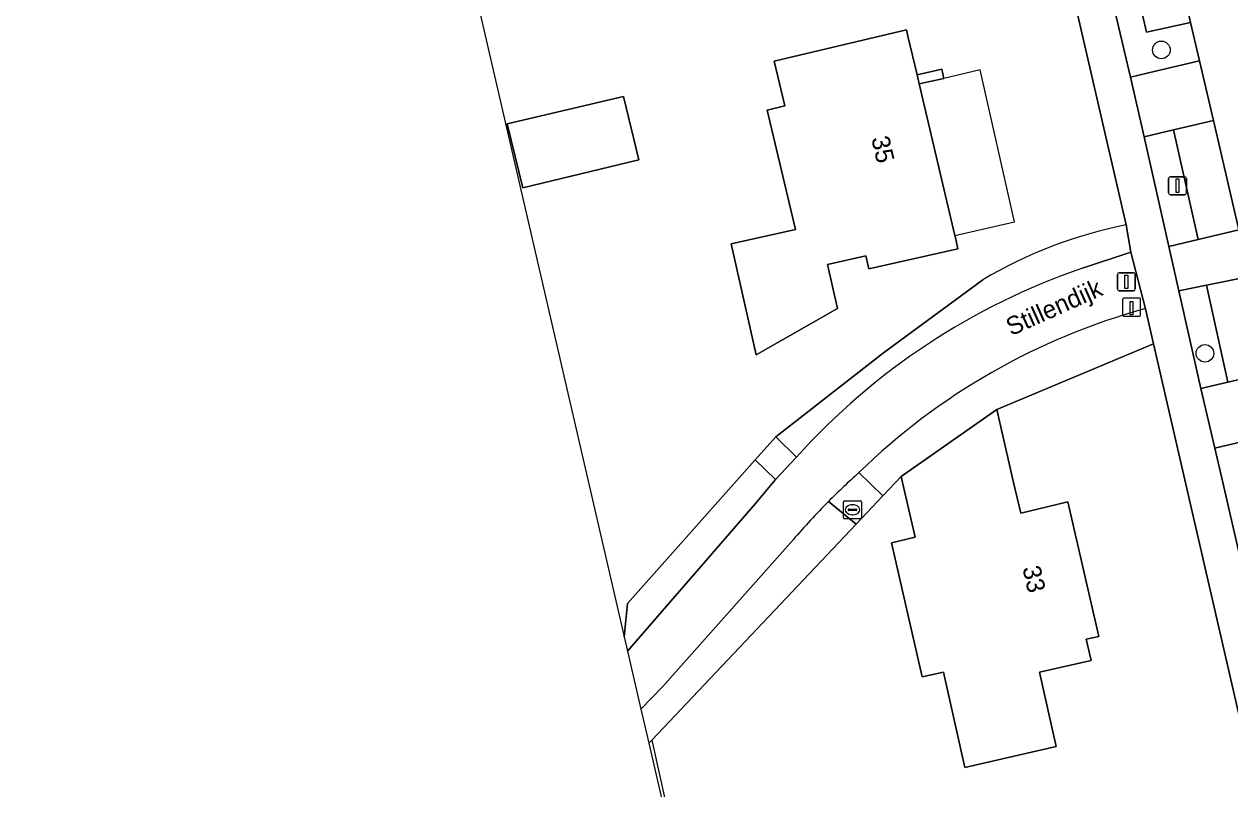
# Model space of a CAD drawing. Extents: x 156412 to 157779, y 382335 to 383768.
# Drawn here: x 156633.8 to 156700.6, y 382733 to 382775.4 of the extents above; entities that cross this region are included whole.
import ezdxf

# ---------------------------------------------------------------- set-up
doc = ezdxf.new("R2010")
doc.units = 0
for name, color, linetype in [('IMGEO_Afsluitpaal', 7, 'Continuous'), ('IMGEO_Berm_groen', 7, 'Continuous'), ('IMGEO_Boom', 7, 'Continuous'), ('IMGEO_Erf', 7, 'Continuous'), ('IMGEO_Fietspad_gesloten', 7, 'Continuous'), ('IMGEO_Fietspad_open', 7, 'Continuous'), ('IMGEO_Hek', 7, 'Continuous'), ('IMGEO_Kolk', 7, 'Continuous'), ('IMGEO_Lichtmast', 7, 'Continuous'), ('IMGEO_Muur', 7, 'Continuous'), ('IMGEO_Openbare_ruimte_label', 7, 'Continuous'), ('IMGEO_Paal', 7, 'Continuous'), ('IMGEO_Pand', 7, 'Continuous'), ('IMGEO_Pand_nummerreeks', 7, 'Continuous'), ('IMGEO_Pand_overbouw', 7, 'Continuous'), ('IMGEO_Parkeervlak_halfverhard', 7, 'Continuous'), ('IMGEO_Rijbaan_lokaal_gesloten', 7, 'Continuous'), ('IMGEO_Rijbaan_lokaal_open', 7, 'Continuous'), ('IMGEO_Voetpad_open', 7, 'Continuous')]:
    doc.layers.add(name, color=color, linetype=linetype)

msp = doc.modelspace()

# ---------------------------------------------------------------- linework, layer by layer
at = {"layer": 'IMGEO_Afsluitpaal'}
for p, q in [((156694.397, 382760.72), (156694.397, 382761.52)), ((156694.397, 382761.52), (156694.397, 382760.72)), ((156694.497, 382761.62), (156695.287, 382761.62)), ((156695.287, 382761.62), (156694.497, 382761.62)), ((156695.387, 382761.52), (156695.387, 382760.72)), ((156695.387, 382760.72), (156695.387, 382761.52)), ((156695.287, 382760.62), (156694.497, 382760.62)), ((156694.497, 382760.62), (156695.287, 382760.62))]:
    msp.add_line(p, q, dxfattribs=at)
msp.add_lwpolyline([(156694.817, 382761.495), (156694.967, 382761.495), (156694.967, 382760.745), (156694.817, 382760.745), (156694.817, 382761.495)], dxfattribs=at)
for centre, start, end in [((156694.497, 382761.52), 90, 180), ((156694.497, 382761.52), 90, 180), ((156695.287, 382761.52), 0, 90), ((156695.287, 382761.52), 360, 90), ((156694.497, 382760.72), 180, 270), ((156694.497, 382760.72), 180, 270), ((156695.287, 382760.72), 270, 0), ((156695.287, 382760.72), 270, 0)]:
    msp.add_arc(centre, 0.1, start, end, dxfattribs=at)
at = {"layer": 'IMGEO_Berm_groen'}
for points in [[(156695.215, 382789.506), (156692.782, 382788.931), (156691.321, 382788.585), (156695.122, 382772.473), (156696.517, 382772.802), (156698.95, 382773.376), (156698.458, 382775.501), (156696.018, 382774.957), (156693.309, 382786.654), (156695.744, 382787.222)], [(156697.512, 382769.539), (156695.881, 382769.156), (156697.255, 382763.084), (156698.872, 382763.466)], [(156699.337, 382760.93), (156697.809, 382760.618), (156699.031, 382755.211), (156700.512, 382755.552)], [(156701.278, 382752.242), (156699.805, 382751.887), (156700.241, 382750), (156701.911, 382742.773), (156703.385, 382743.12)], [(156667.231, 382740.642), (156674.321, 382748.836), (156675.444, 382750.152), (156674.316, 382751.245), (156667.239, 382743.282), (156667.046, 382741.442)]]:
    msp.add_lwpolyline(points, close=True, dxfattribs=at)
for points in [[(156692.46, 382761.877), (156695.147, 382762.767), (156694.882, 382764.275)], [(156686.93, 382761.227), (156681.422, 382757.184), (156675.463, 382752.525), (156676.602, 382751.4)], [(156696.399, 382757.676), (156695.949, 382759.629)], [(156680.063, 382750.539), (156681.391, 382749.254), (156682.407, 382750.328), (156687.706, 382754.041), (156696.399, 382757.676)], [(156668.411, 382735.538), (156668.582, 382735.705), (156679.903, 382747.679), (156678.372, 382748.938)], [(156676.416, 382746.819), (156669.164, 382738.669), (156667.976, 382737.419), (156668.411, 382735.538)]]:
    msp.add_lwpolyline(points, dxfattribs=at)
for centre, radius, start, end in [((156699.833, 382739.461), 25.304, 101.28401, 120.65963), ((156704.737, 382726.055), 37.868, 108.91757, 137.986), ((156705.623, 382724.296), 36.634, 105.31209, 134.24445), ((156710.589, 382717.237), 45.198, 135.46248, 139.11874)]:
    msp.add_arc(centre, radius, start, end, dxfattribs=at)
at = {"layer": 'IMGEO_Boom'}
for centre in [(156696.837, 382773.973), (156699.253, 382757.152)]:
    msp.add_circle(centre, 0.489, dxfattribs=at)
at = {"layer": 'IMGEO_Erf'}
for points in [[(156662.663, 382894.621), (156655.658, 382892.624), (156652.152, 382891.665), (156646.148, 382889.742), (156640.021, 382887.678), (156636.864, 382886.529), (156633.896, 382885.409), (156633.769, 382885.37), (156667.046, 382741.442)], [(156694.882, 382764.275), (156665.21, 382892.732)], [(156667.046, 382741.442), (156667.239, 382743.282), (156674.316, 382751.245), (156675.463, 382752.525), (156681.422, 382757.184), (156686.93, 382761.227)], [(156708.634, 382704.563), (156696.399, 382757.676), (156687.706, 382754.041), (156688.641, 382750), (156689.036, 382748.295), (156691.645, 382748.927), (156693.368, 382741.448), (156692.667, 382741.304), (156692.938, 382740.131), (156690.082, 382739.476), (156690.997, 382735.351), (156685.938, 382734.188), (156684.748, 382739.475), (156683.577, 382739.212), (156681.866, 382746.654), (156683.182, 382746.956), (156682.482, 382750), (156682.407, 382750.328), (156681.391, 382749.254), (156679.903, 382747.679), (156668.582, 382735.705), (156668.411, 382735.538), (156678.18, 382693.285), (156690.465, 382640.147)]]:
    msp.add_lwpolyline(points, dxfattribs=at)
for points in [[(156682.696, 382775.089), (156682.778, 382774.743), (156683.29, 382772.589), (156684.664, 382772.906), (156684.778, 382772.397), (156683.405, 382772.098), (156685.382, 382763.692), (156685.394, 382763.64), (156685.55, 382762.951), (156680.611, 382761.841), (156680.449, 382762.563), (156678.322, 382762.085), (156678.867, 382759.634), (156674.363, 382757.07), (156672.986, 382763.218), (156676.548, 382764.016), (156674.976, 382770.634), (156675.949, 382770.866), (156675.36, 382773.347)], [(156667.006, 382771.399), (156667.853, 382767.888), (156661.419, 382766.33), (156660.564, 382769.877)]]:
    msp.add_lwpolyline(points, close=True, dxfattribs=at)
msp.add_arc((156699.833, 382739.461), 25.304, 101.28401, 120.65963, dxfattribs=at)
at = {"layer": 'IMGEO_Fietspad_gesloten'}
for points in [[(156695.949, 382759.629), (156695.147, 382762.767), (156692.46, 382761.877)], [(156676.602, 382751.4), (156675.444, 382750.152), (156674.321, 382748.836), (156667.231, 382740.642), (156667.976, 382737.419)], [(156667.976, 382737.419), (156669.164, 382738.669), (156676.416, 382746.819)]]:
    msp.add_lwpolyline(points, dxfattribs=at)
for centre, radius, start, end in [((156704.737, 382726.055), 37.868, 108.91757, 137.986), ((156705.623, 382724.296), 36.634, 105.31209, 134.24445), ((156710.608, 382716.584), 45.672, 131.97317, 134.89479), ((156710.589, 382717.237), 45.198, 135.46248, 139.11874)]:
    msp.add_arc(centre, radius, start, end, dxfattribs=at)
at = {"layer": 'IMGEO_Fietspad_open'}
msp.add_lwpolyline([(156701.127, 382763.998), (156698.872, 382763.466), (156697.255, 382763.084), (156697.809, 382760.618), (156699.337, 382760.93), (156701.724, 382761.418)], close=True, dxfattribs=at)
at = {"layer": 'IMGEO_Hek'}
for points in [[(156687.706, 382754.041), (156696.399, 382757.676)], [(156667.239, 382743.282), (156674.316, 382751.245)], [(156682.407, 382750.328), (156681.391, 382749.254)], [(156681.391, 382749.254), (156679.903, 382747.679)], [(156679.903, 382747.679), (156668.582, 382735.705), (156673.316, 382714.324)], [(156667.046, 382741.442), (156667.239, 382743.282)]]:
    msp.add_lwpolyline(points, dxfattribs=at)
at = {"layer": 'IMGEO_Kolk'}
for p, q in [((156679.283, 382748.979), (156680.135, 382748.979)), ((156679.208, 382748.053), (156679.208, 382748.905)), ((156679.467, 382748.473), (156679.467, 382748.485)), ((156679.905, 382748.436), (156679.507, 382748.436)), ((156679.51, 382748.522), (156679.908, 382748.522)), ((156679.696, 382748.759), (156679.721, 382748.759)), ((156679.951, 382748.485), (156679.951, 382748.473)), ((156680.209, 382748.905), (156680.209, 382748.053)), ((156680.135, 382747.979), (156679.283, 382747.979)), ((156679.719, 382748.199), (156679.694, 382748.199))]:
    msp.add_line(p, q, dxfattribs=at)
for points in [[(156679.283, 382748.979), (156680.135, 382748.979)], [(156679.208, 382748.053), (156679.208, 382748.905)], [(156680.209, 382748.905), (156680.209, 382748.053)], [(156680.135, 382747.979), (156679.283, 382747.979)]]:
    msp.add_lwpolyline(points, dxfattribs=at)
for centre, radius, start, end in [((156679.285, 382748.903), 0.0765, 91.55205, 178.44795), ((156679.285, 382748.903), 0.0765, 91.55205, 178.44795), ((156680.133, 382748.903), 0.0765, 1.55205, 88.44795), ((156680.133, 382748.903), 0.0765, 1.55205, 88.44795), ((156679.507, 382748.482), 0.0403, 85.87752, 175.75265), ((156679.504, 382748.472), 0.0366, 178.93798, 274.71019), ((156679.908, 382748.479), 0.043, 264.86636, 352.45326), ((156679.912, 382748.484), 0.0386, 1.73085, 96.63898), ((156679.285, 382748.055), 0.0765, 181.55205, 268.44795), ((156679.285, 382748.055), 0.0765, 181.55205, 268.44795), ((156680.133, 382748.055), 0.0765, 271.55205, 358.44795), ((156680.133, 382748.055), 0.0765, 271.55205, 358.44795)]:
    msp.add_arc(centre, radius, start, end, dxfattribs=at)
for centre, major_axis, ratio, start_param, end_param in [((156679.695, 382748.479), (-0.387, 0.002), 0.722429, 4.712389, 7.853982), ((156679.72, 382748.479), (-0.39, 0.002), 0.717154, 1.570796, 4.712389)]:
    msp.add_ellipse(centre, major_axis=major_axis, ratio=ratio, start_param=start_param, end_param=end_param, dxfattribs=at)
at = {"layer": 'IMGEO_Lichtmast'}
for p, q in [((156697.234, 382766.046), (156697.234, 382766.846)), ((156697.234, 382766.846), (156697.234, 382766.046)), ((156697.334, 382766.946), (156698.124, 382766.946)), ((156698.124, 382766.946), (156697.334, 382766.946)), ((156698.224, 382766.846), (156698.224, 382766.046)), ((156698.224, 382766.046), (156698.224, 382766.846)), ((156698.124, 382765.946), (156697.334, 382765.946)), ((156697.334, 382765.946), (156698.124, 382765.946))]:
    msp.add_line(p, q, dxfattribs=at)
msp.add_lwpolyline([(156697.654, 382766.821), (156697.804, 382766.821), (156697.804, 382766.071), (156697.654, 382766.071), (156697.654, 382766.821)], dxfattribs=at)
for centre, start, end in [((156697.334, 382766.846), 90, 180), ((156697.334, 382766.846), 90, 180), ((156698.124, 382766.846), 0, 90), ((156698.124, 382766.846), 360, 90), ((156697.334, 382766.046), 180, 270), ((156697.334, 382766.046), 180, 270), ((156698.124, 382766.046), 270, 0), ((156698.124, 382766.046), 270, 0)]:
    msp.add_arc(centre, 0.1, start, end, dxfattribs=at)
at = {"layer": 'IMGEO_Muur'}
msp.add_lwpolyline([(156684.664, 382772.906), (156683.29, 382772.589), (156683.405, 382772.098), (156684.778, 382772.397)], close=True, dxfattribs=at)
at = {"layer": 'IMGEO_Paal'}
for p, q in [((156694.686, 382760.129), (156694.686, 382759.288)), ((156694.686, 382760.129), (156694.686, 382759.288)), ((156695.602, 382760.213), (156694.761, 382760.213)), ((156695.602, 382760.213), (156694.761, 382760.213)), ((156695.686, 382759.297), (156695.686, 382760.138)), ((156695.686, 382759.297), (156695.686, 382760.138)), ((156694.77, 382759.213), (156695.611, 382759.213)), ((156694.77, 382759.213), (156695.611, 382759.213))]:
    msp.add_line(p, q, dxfattribs=at)
msp.add_lwpolyline([(156695.101, 382760.026), (156695.261, 382760.026), (156695.261, 382759.293), (156695.101, 382759.293), (156695.101, 382760.026)], dxfattribs=at)
for centre, start, end in [((156694.764, 382760.135), 92.4484, 184.28452), ((156694.764, 382760.135), 92.4484, 184.28452), ((156695.608, 382760.135), 2.4484, 94.28452), ((156695.608, 382760.135), 2.4484, 94.28452), ((156694.764, 382759.291), 182.4484, 274.28452), ((156694.764, 382759.291), 182.4484, 274.28452), ((156695.608, 382759.291), 272.4484, 4.28452), ((156695.608, 382759.291), 272.4484, 4.28452)]:
    msp.add_arc(centre, 0.0779, start, end, dxfattribs=at)
at = {"layer": 'IMGEO_Pand'}
for points in [[(156683.405, 382772.098), (156683.29, 382772.589), (156682.778, 382774.743), (156682.696, 382775.089), (156675.36, 382773.347), (156675.949, 382770.866), (156674.976, 382770.634), (156676.548, 382764.016), (156672.986, 382763.218), (156674.363, 382757.07), (156678.867, 382759.634), (156678.322, 382762.085), (156680.449, 382762.563), (156680.611, 382761.841), (156685.55, 382762.951), (156685.394, 382763.64), (156685.382, 382763.692)], [(156661.419, 382766.33), (156667.853, 382767.888), (156667.006, 382771.399), (156660.564, 382769.877)], [(156687.706, 382754.041), (156682.407, 382750.328), (156682.482, 382750), (156683.182, 382746.956), (156681.866, 382746.654), (156683.577, 382739.212), (156684.748, 382739.475), (156685.938, 382734.188), (156690.997, 382735.351), (156690.082, 382739.476), (156692.938, 382740.131), (156692.667, 382741.304), (156693.368, 382741.448), (156691.645, 382748.927), (156689.036, 382748.295), (156688.641, 382750)]]:
    msp.add_lwpolyline(points, close=True, dxfattribs=at)
at = {"layer": 'IMGEO_Pand_overbouw'}
msp.add_lwpolyline([(156686.79, 382772.863), (156684.778, 382772.397), (156683.405, 382772.098), (156685.382, 382763.692), (156688.693, 382764.44)], close=True, dxfattribs=at)
at = {"layer": 'IMGEO_Parkeervlak_halfverhard'}
for points in [[(156695.744, 382787.222), (156693.309, 382786.654), (156696.018, 382774.957), (156698.458, 382775.501)], [(156699.724, 382770.058), (156697.512, 382769.539), (156698.872, 382763.466), (156701.127, 382763.998)], [(156701.724, 382761.418), (156699.337, 382760.93), (156700.512, 382755.552), (156702.948, 382756.114)]]:
    msp.add_lwpolyline(points, close=True, dxfattribs=at)
at = {"layer": 'IMGEO_Rijbaan_lokaal_gesloten'}
msp.add_lwpolyline([(156691.921, 382803.833), (156694.033, 382794.649), (156694.767, 382791.455), (156695.215, 382789.506), (156695.744, 382787.222), (156698.458, 382775.501), (156698.95, 382773.376), (156699.724, 382770.058), (156701.127, 382763.998)], dxfattribs=at)
at = {"layer": 'IMGEO_Rijbaan_lokaal_open'}
for points in [[(156698.95, 382773.376), (156696.517, 382772.802), (156695.122, 382772.473), (156695.881, 382769.156), (156697.512, 382769.539), (156699.724, 382770.058)], [(156702.948, 382756.114), (156700.512, 382755.552), (156699.031, 382755.211), (156699.805, 382751.887), (156701.278, 382752.242), (156703.708, 382752.829)]]:
    msp.add_lwpolyline(points, close=True, dxfattribs=at)
at = {"layer": 'IMGEO_Voetpad_open'}
for points in [[(156665.21, 382892.732), (156694.882, 382764.275), (156695.147, 382762.767), (156695.949, 382759.629), (156696.399, 382757.676), (156708.634, 382704.563), (156717.566, 382666.506), (156725.025, 382634.25), (156725.115, 382633.86), (156726.112, 382629.552), (156727.385, 382624.03), (156727.839, 382622.057), (156731.446, 382606.382)], [(156701.911, 382742.773), (156700.241, 382750), (156699.805, 382751.887), (156699.031, 382755.211), (156697.809, 382760.618), (156697.255, 382763.084), (156695.881, 382769.156), (156695.122, 382772.473), (156691.321, 382788.585), (156692.782, 382788.931), (156695.215, 382789.506), (156694.767, 382791.455), (156690.864, 382790.532), (156690.119, 382793.734), (156688.01, 382802.932)], [(156678.372, 382748.938), (156679.903, 382747.679), (156681.391, 382749.254), (156680.063, 382750.539)]]:
    msp.add_lwpolyline(points, dxfattribs=at)
msp.add_lwpolyline([(156675.463, 382752.525), (156674.316, 382751.245), (156675.444, 382750.152), (156676.602, 382751.4)], close=True, dxfattribs=at)
msp.add_arc((156710.608, 382716.584), 45.672, 131.97317, 134.89479, dxfattribs=at)

# ---------------------------------------------------------------- texts
at = {"layer": 'IMGEO_Openbare_ruimte_label'}
msp.add_text('Stillendijk', height=1, rotation=24.06498, dxfattribs=at).set_placement((156688.504, 382758.101))
at = {"layer": 'IMGEO_Pand_nummerreeks'}
for s, rotation, p in [('35', 283.22939, (156680.741, 382769.074)), ('33', 282.97335, (156689.125, 382745.256))]:
    msp.add_text(s, height=1, rotation=rotation, dxfattribs=at).set_placement(p)

doc.saveas('drawing.dxf')
